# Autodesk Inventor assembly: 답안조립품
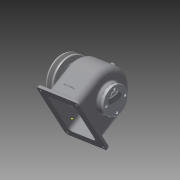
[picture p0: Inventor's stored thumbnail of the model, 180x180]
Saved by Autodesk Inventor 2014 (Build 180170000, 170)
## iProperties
Created: 2016-01
Part Number: 답안조립품
Document SubType Name: Assembly
Designer: 04
Author: 04
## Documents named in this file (15)
- C:\Users\04\Desktop\460105V1029\답안조립품.iam
- C:\Users\04\Desktop\460105V1029\V-벨트풀리.ipt
- C:\Users\04\Desktop\460105V1029\뒤커버.ipt
- C:\Users\04\Desktop\460105V1029\멈춤나사 - M4x10.ipt
- C:\Users\04\Desktop\460105V1029\베어링 6203.ipt
- C:\Users\04\Desktop\460105V1029\본체.ipt
- C:\Users\04\Desktop\460105V1029\볼트 M3 x 8.ipt
- C:\Users\04\Desktop\460105V1029\부시1.ipt
- C:\Users\04\Desktop\460105V1029\부시2.ipt
- C:\Users\04\Desktop\460105V1029\스퍼기어.ipt
- C:\Users\04\Desktop\460105V1029\앞커버.ipt
- C:\Users\04\Desktop\460105V1029\오일씰 28 40 8.ipt
- C:\Users\04\Desktop\460105V1029\축.ipt
- C:\Users\04\Desktop\460105V1029\키 - 5 x 5 x 18.ipt
- C:\Users\04\Desktop\460105V1029\키 - 6 x 6 x 22.ipt
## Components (2 placed, 2 different names)
1. V-벨트풀리:1
2. ISO 4762 M3 x 8:1
